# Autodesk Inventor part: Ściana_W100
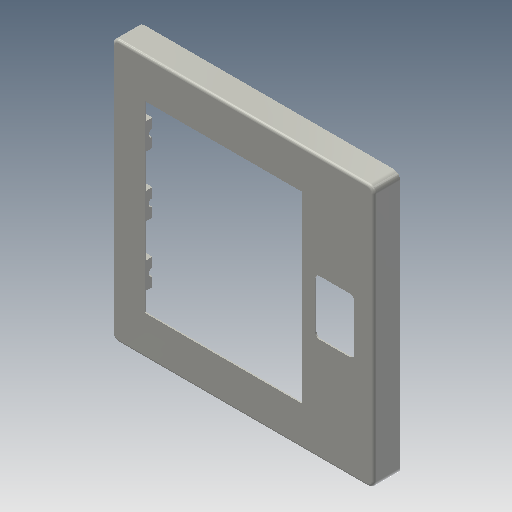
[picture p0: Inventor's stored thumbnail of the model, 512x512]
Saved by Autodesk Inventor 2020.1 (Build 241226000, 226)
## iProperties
Created: 2005-10
Part Number: Ściana_W100
Document SubType Name: Modeling
Designer: F.Stasiak
Density: 1 g/cm^3
Material: Ogólny
Appearance: Gładkie — w kolorze kości słoniowej
Manager: www.cadconsulting.pl
Company: Fabian Stasiak CAD Consulting
Author: F.Stasiak
Subject: Zbiór ćwiczeń. Autodesk Inventor 2020. Kurs podstawowy
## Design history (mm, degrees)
sketch "Szkic1"
  geometry: L1 (-100, 100)-(100, 100); L2 (100, 100)-(100, -100); L3 (100, -100)-(-100, -100); L4 (-100, -100)-(-100, 100); L5 (0, 100)-(0, -100); 2 further points
  constraints: 10 end point, 3 midpoint, 2 parallel, 1 coincident, 1 horizontal, 1 perpendicular
  dimensions: "d0" = 200 distance of L2.end L3.end; "d1" = 200 distance of L3.end L1.start
extrude "Wyciągnięcie proste1" new body sketch "Szkic1" distance "d2" = 20; taper "d3" = 0 deg
fillet "Zaokrąglenie1" dims "d4" = 5
fillet "Zaokrąglenie2" dims "d5" = 2
feature "Skorupa1" dims "d6" = 1
sketch "Szkic2"
  geometry: L1 (-100, 95)-(-100, -95) reference; L2 (95, 100)-(-95, 100) reference; L3 (100, -95)-(100, 95) reference; L4 (-95, -100)-(95, -100) reference; L5 (-75, 70)-(45, 70); L6 (45, 70)-(45, -70); L7 (45, -70)-(-75, -70); L8 (-75, -70)-(-75, 70)
  constraints: 8 end point, 2 parallel, 1 horizontal, 1 perpendicular
  dimensions: "d7" = 120 distance of L6.end L7.end; "d8" = 140 distance of L7.end L5.start; "d9" = 25 distance between parallel lines of L8 L1; "d10" = 30 distance between parallel lines of L4 L7
extrude "Wyciągnięcie proste2" cut sketch "Szkic2" extent not by distance; stored distance "d11" = 10; taper "d12" = 0 deg
sketch "Szkic3"
  geometry: L1 (50, -168)-(50, -28) reference; L2 (45, -134)-(50, -134); L3 (50, -134)-(50, -154); L4 (50, -154)-(45, -154); L5 (45, -154)-(45, -134)
  constraints: 8 end point, 2 parallel, 1 horizontal, 1 perpendicular, 1 point on line
  dimensions: "d13" = 5 distance of L3.end L4.end; "d14" = 20 distance of L4.end L2.start; "d15" = 14 distance from line of L1.start L4
extrude "Wyciągnięcie proste3" join sketch "Szkic3" distance "d16" = 5; taper "d17" = 0 deg
sketch "Szkic4"
  geometry: L1 (0, 0)-(0, 20) reference; C1 r 3 at (0, 10)
  constraints: 1 centre point, 1 midpoint
  dimensions: "d18" = 6 diameter of C1
extrude "Wyciągnięcie proste4" cut sketch "Szkic4" stored distance "d19" = 4; taper "d20" = 0 deg
node "Płaszczyzna konstrukcyjna1"
pattern_linear "Szyk prostokątny1" dims "d23" = 46, "d26" = 125
sketch "Szkic5"
  geometry: L1 (50, -88)-(50, -62) reference; L2 (-5, -3)-(-5, -193) reference; L3 (10, -77)-(40, -77); L4 (40, -77)-(40, -119); L5 (40, -119)-(10, -119); L6 (10, -119)-(10, -77); L7 (45, -101)-(45, -95) reference; L8 (10, -98)-(40, -98); 1 further point
  constraints: 10 end point, 3 midpoint, 2 parallel, 1 horizontal, 1 perpendicular, 1 point on line
  dimensions: "d27" = 10 distance between parallel lines of L1 L4; "d28" = 15 distance between parallel lines of L2 L6; "d29" = 42 distance of L5.end L3.start
extrude "Wyciągnięcie proste5" cut sketch "Szkic5" extent not by distance; stored distance "d30" = 4; taper "d31" = 0 deg
sketch "Szkic6"
  geometry: L1 (0.097, -88)-(5.097, -88); L2 (5.097, -88)-(5.097, -108); L3 (5.097, -108)-(0.097, -108); L4 (0.097, -108)-(0.097, -88); L5 (50, -108)-(45, -108) reference; L6 (45, -88)-(50, -88) reference
  constraints: 8 end point, 2 collinear, 2 parallel, 1 horizontal, 1 perpendicular
  dimensions: "d32" = 5 distance of L2.end L3.end
extrude "Wyciągnięcie proste6" join sketch "Szkic6" distance "d33" = 5; taper "d34" = 0 deg
sketch "Szkic7"
  geometry: C1 r 3 at (0, 10); A1 r 3 centre (0, 10) between (0, 7) and (0, 13) reference
  constraints: 1 centre point, 1 coincident, 1 concentric
extrude "Wyciągnięcie proste7" cut sketch "Szkic7" stored distance "d35" = 4; taper "d36" = 0 deg
pattern_linear "Szyk prostokątny2" dims "d39" = 46, "d42" = 46
fillet "Zaokrąglenie3" dims "d43" = 3.5
node "Bryła1"
node "Korpusy bryłowe"
node "Korpusy powierzchniowe"
